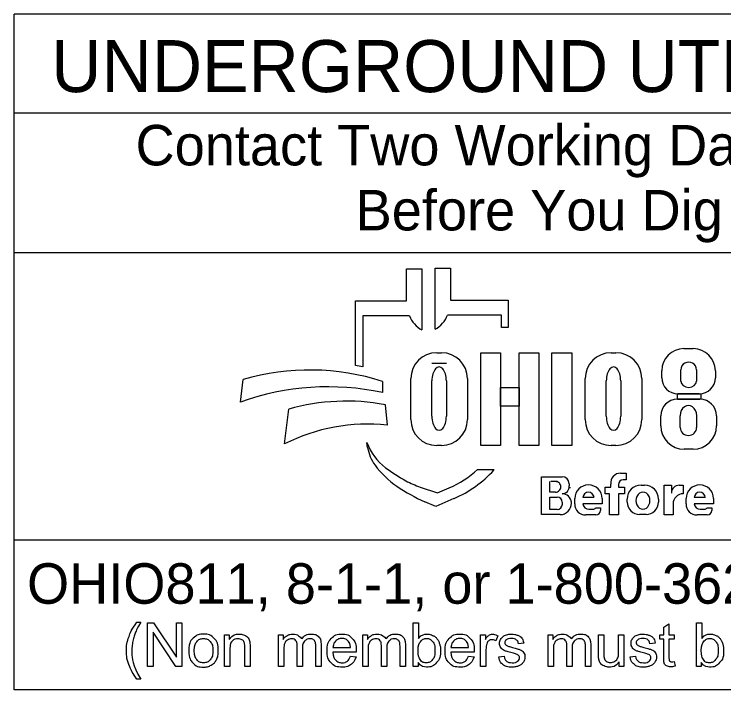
# Model space of a CAD drawing. Extents: x -3.3 to 34, y 0 to 56.8.
# Drawn here: x 2.378 to 4.831, y 1.905 to 4.243 of the extents above; entities that cross this region are included whole.
import ezdxf

# ---------------------------------------------------------------- set-up
doc = ezdxf.new("R2010")
doc.units = 0
doc.layers.add('SH_Data', color=7, linetype='Continuous')
doc.layers.add('SH_Major_Grid_Line', color=7, linetype='Continuous')

msp = doc.modelspace()

# ---------------------------------------------------------------- linework, layer by layer
at = {"layer": 'SH_Data'}
for p, q in [((2.3775, 1.9053), (2.3775, 4.2428)), ((6.6275, 4.2428), (2.3775, 4.2428)), ((2.3775, 3.9012), (6.6275, 3.9012)), ((2.3775, 3.4178), (6.6275, 3.4178)), ((6.6275, 2.4232), (2.3775, 2.4232)), ((6.6275, 1.9053), (2.3775, 1.9053))]:
    msp.add_line(p, q, dxfattribs=at)
at = {"layer": 'SH_Major_Grid_Line'}
for p, q in [((3.7335, 3.2508), (3.7335, 3.3623)), ((3.7335, 3.3623), (3.7872, 3.3623)), ((3.7872, 3.3623), (3.7872, 3.1502)), ((3.8329, 3.1525), (3.8329, 3.3646)), ((3.8329, 3.3646), (3.8865, 3.3646)), ((3.8865, 3.3646), (3.8865, 3.2531)), ((3.5576, 3.0269), (3.5576, 3.2508)), ((3.5576, 3.2508), (3.7335, 3.2508)), ((3.8865, 3.2531), (4.0857, 3.2531)), ((4.0857, 3.2531), (4.0857, 3.1593)), ((3.5828, 3.1994), (3.5828, 3.0225)), ((3.7439, 3.1994), (3.5828, 3.1994)), ((4.0625, 3.2017), (3.8761, 3.2017)), ((4.0625, 3.1593), (4.0625, 3.2017)), ((4.0857, 3.1593), (4.0625, 3.1593)), ((3.8385, 3.0716), (3.8551, 3.0716)), ((4.4416, 3.0716), (4.4581, 3.0716)), ((4.6931, 3.0856), (4.7258, 3.0856)), ((3.8718, 3.0346), (3.822, 3.0346)), ((4.6168, 2.985), (4.6168, 3.0093)), ((4.683, 2.9736), (4.683, 3.0129)), ((4.7371, 3.0129), (4.7371, 2.9736)), ((4.8022, 3.0093), (4.8022, 2.985)), ((3.1602, 2.9006), (3.1696, 2.9787)), ((3.6509, 2.9722), (3.6509, 2.9334)), ((3.7491, 2.8401), (3.7491, 2.9821)), ((3.822, 2.8515), (3.822, 2.9739)), ((3.8718, 2.9739), (3.8718, 2.8515)), ((3.9445, 2.9821), (3.9445, 2.8401)), ((4.3521, 2.8401), (4.3521, 2.9821)), ((4.425, 2.8515), (4.425, 2.9739)), ((4.4748, 2.9739), (4.4748, 2.8515)), ((4.5476, 2.9821), (4.5476, 2.8401)), ((4.7462, 2.929), (4.6728, 2.929)), ((4.671, 2.9107), (4.7483, 2.9107)), ((3.312, 2.7561), (3.3267, 2.8762)), ((3.6608, 2.8916), (3.6671, 2.8207)), ((4.6131, 2.8188), (4.6131, 2.8528)), ((4.6806, 2.8128), (4.6806, 2.8537)), ((4.7374, 2.8537), (4.7374, 2.8128)), ((4.8062, 2.8528), (4.8062, 2.8188)), ((3.5997, 2.7432), (3.5967, 2.7611)), ((3.8551, 2.7507), (3.8385, 2.7507)), ((4.4581, 2.7507), (4.4416, 2.7507)), ((4.7252, 2.7378), (4.6941, 2.7378)), ((3.98, 2.6673), (4.0375, 2.6673)), ((4.4739, 2.6551), (4.4934, 2.6551)), ((4.4934, 2.6551), (4.4934, 2.6321)), ((4.2013, 2.5115), (4.2013, 2.6423)), ((4.2013, 2.6423), (4.2725, 2.6423)), ((4.2293, 2.5888), (4.2293, 2.6257)), ((4.2545, 2.6257), (4.2332, 2.6257)), ((4.4934, 2.6316), (4.4832, 2.6316)), ((3.7816, 2.6069), (3.841, 2.5864)), ((3.841, 2.5864), (3.8821, 2.6042)), ((4.2963, 2.6185), (4.2963, 2.6106)), ((4.4213, 2.5837), (4.4213, 2.6067)), ((4.4213, 2.6067), (4.4406, 2.6067)), ((4.4406, 2.6067), (4.4406, 2.6171)), ((4.4667, 2.6151), (4.4667, 2.6067)), ((4.4667, 2.6067), (4.4883, 2.6067)), ((4.4883, 2.6067), (4.4883, 2.5837)), ((4.5451, 2.6133), (4.5573, 2.6133)), ((4.6254, 2.5103), (4.6254, 2.613)), ((4.6254, 2.613), (4.6499, 2.613)), ((4.6499, 2.613), (4.6499, 2.5862)), ((4.6772, 2.613), (4.691, 2.613)), ((4.691, 2.613), (4.691, 2.5834)), ((4.2487, 2.5888), (4.2293, 2.5888)), ((4.4362, 2.5837), (4.4213, 2.5837)), ((4.4362, 2.5103), (4.4362, 2.5837)), ((4.4883, 2.5837), (4.4667, 2.5837)), ((4.4667, 2.5837), (4.4667, 2.5103)), ((3.835, 2.5394), (3.7976, 2.5559)), ((3.8983, 2.5669), (3.835, 2.5394)), ((4.2293, 2.5294), (4.2293, 2.5722)), ((4.2293, 2.5722), (4.2548, 2.5722)), ((4.2729, 2.5541), (4.2729, 2.5478)), ((4.3159, 2.5483), (4.3159, 2.5667)), ((4.3824, 2.5707), (4.3439, 2.5707)), ((4.4104, 2.5667), (4.4104, 2.5491)), ((4.4973, 2.5547), (4.4973, 2.5654)), ((4.6051, 2.5654), (4.6051, 2.5547)), ((4.7008, 2.5483), (4.7008, 2.5667)), ((4.7674, 2.5707), (4.7288, 2.5707)), ((4.7953, 2.5667), (4.7953, 2.5491)), ((4.2546, 2.5294), (4.2293, 2.5294)), ((4.3043, 2.5512), (4.3043, 2.5509)), ((4.4104, 2.5491), (4.344, 2.5491)), ((4.3649, 2.5298), (4.379, 2.5298)), ((4.3876, 2.5354), (4.4045, 2.5354)), ((4.4045, 2.5354), (4.4045, 2.5256)), ((4.6559, 2.5485), (4.6559, 2.5103)), ((4.7953, 2.5491), (4.7289, 2.5491)), ((4.7498, 2.5298), (4.7639, 2.5298)), ((4.7725, 2.5354), (4.7894, 2.5354)), ((4.7894, 2.5354), (4.7894, 2.5256)), ((4.265, 2.5115), (4.2013, 2.5115)), ((4.3892, 2.5103), (4.3538, 2.5103)), ((4.4667, 2.5103), (4.4362, 2.5103)), ((4.5623, 2.5119), (4.5401, 2.5119)), ((4.6559, 2.5103), (4.6254, 2.5103)), ((4.7742, 2.5103), (4.7388, 2.5103))]:
    msp.add_line(p, q, dxfattribs=at)
for points in [[(3.991, 3.0706), (4.0589, 3.0706), (4.0589, 2.7506), (3.991, 2.7506)], [(4.1231, 3.0706), (4.1911, 3.0706), (4.1911, 2.7506), (4.1231, 2.7506)], [(4.2364, 3.0706), (4.3052, 3.0706), (4.3052, 2.7506), (4.2364, 2.7506)], [(4.0589, 2.9507), (4.1231, 2.9507), (4.1231, 2.8867), (4.0589, 2.8867)], [(4.6706, 2.929), (4.7523, 2.929), (4.7523, 2.9106), (4.6706, 2.9106)]]:
    msp.add_lwpolyline(points, close=True, dxfattribs=at)
for points in [[(2.8021, 2.1391), (2.8153, 2.1391)], [(2.8389, 1.9864), (2.8389, 2.1366), (2.8592, 2.1366), (2.9382, 2.0186), (2.9382, 2.1366), (2.9572, 2.1366), (2.9572, 1.9864), (2.9369, 1.9864), (2.8579, 2.1044), (2.8579, 1.9864), (2.8389, 1.9864)], [(3.7743, 1.9864), (3.7573, 1.9864), (3.7573, 2.1366), (3.7757, 2.1366), (3.7757, 2.0831)], [(4.7534, 1.9864), (4.7363, 1.9864), (4.7363, 2.1366), (4.7548, 2.1366), (4.7548, 2.0831)], [(4.6233, 2.0183), (4.6233, 2.081), (4.6097, 2.081), (4.6097, 2.0953), (4.6233, 2.0953), (4.6233, 2.1222), (4.6417, 2.1333), (4.6417, 2.0953), (4.6601, 2.0953), (4.6601, 2.081), (4.6417, 2.081), (4.6417, 2.0172)], [(3.1048, 1.9864), (3.1048, 2.0953), (3.1214, 2.0953), (3.1214, 2.0798)], [(3.2912, 1.9864), (3.2912, 2.0953), (3.3077, 2.0953), (3.3077, 2.0799)], [(3.5826, 1.9864), (3.5826, 2.0953), (3.5991, 2.0953), (3.5991, 2.0799)], [(3.9904, 1.9864), (3.9904, 2.0953), (4.007, 2.0953), (4.007, 2.0788)], [(4.0495, 2.0918), (4.043, 2.0747)], [(4.2236, 1.9864), (4.2236, 2.0953), (4.2401, 2.0953), (4.2401, 2.0799)], [(4.3979, 2.0279), (4.3979, 2.0953), (4.4164, 2.0953), (4.4164, 2.0349)], [(4.4676, 2.037), (4.4676, 2.0953), (4.4861, 2.0953), (4.4861, 1.9864), (4.4696, 1.9864)], [(4.1394, 2.0671), (4.1213, 2.0647)], [(4.594, 2.0671), (4.5759, 2.0647)], [(3.1233, 2.0458), (3.1233, 1.9864), (3.1048, 1.9864)], [(3.1932, 2.0533), (3.1932, 1.9864), (3.1748, 1.9864), (3.1748, 2.0526)], [(3.3097, 2.0428), (3.3097, 1.9864), (3.2912, 1.9864)], [(3.3743, 2.0496), (3.3743, 1.9864), (3.3559, 1.9864), (3.3559, 2.0571)], [(3.4388, 2.0611), (3.4388, 1.9864), (3.4203, 1.9864), (3.4203, 2.0549)], [(3.4799, 2.0512), (3.5406, 2.0512)], [(3.601, 2.0428), (3.601, 1.9864), (3.5826, 1.9864)], [(3.6657, 2.0496), (3.6657, 1.9864), (3.6473, 1.9864), (3.6473, 2.0571)], [(3.7301, 2.0611), (3.7301, 1.9864), (3.7117, 1.9864), (3.7117, 2.0549)], [(3.8879, 2.0512), (3.9486, 2.0512)], [(4.0088, 2.0434), (4.0088, 1.9864), (3.9904, 1.9864)], [(4.242, 2.0428), (4.242, 1.9864), (4.2236, 1.9864)], [(4.3067, 2.0496), (4.3067, 1.9864), (4.2883, 1.9864), (4.2883, 2.0571)], [(4.3711, 2.0611), (4.3711, 1.9864), (4.3527, 1.9864), (4.3527, 2.0549)], [(3.56, 2.0361), (3.4788, 2.0361)], [(3.5404, 2.0216), (3.5595, 2.0192)], [(3.968, 2.0361), (3.8868, 2.0361)], [(3.9484, 2.0216), (3.9675, 2.0192)], [(4.053, 2.0189), (4.0712, 2.0218)], [(4.5076, 2.0189), (4.5258, 2.0218)], [(3.7743, 2), (3.7743, 1.9864)], [(4.4696, 1.9864), (4.4696, 2.0025)], [(4.6601, 2.0029), (4.6628, 1.9866)], [(4.7534, 2), (4.7534, 1.9864)], [(2.8153, 1.9422), (2.8021, 1.9422)]]:
    msp.add_lwpolyline(points, dxfattribs=at)
for centre, radius, start, end in [((3.8353, 3.2361), 0.0985, 201.9296, 240.7469), ((3.7847, 3.2385), 0.0985, 299.2531, 338.0704), ((3.8385, 2.9821), 0.0895, 90, 180), ((3.8551, 2.9821), 0.0895, 0, 90), ((4.4416, 2.9821), 0.0895, 90, 180), ((4.4581, 2.9821), 0.0895, 0, 90), ((4.6931, 3.0093), 0.0763, 90, 180), ((4.7258, 3.0093), 0.0763, 0, 90), ((3.4295, 2.2179), 0.8191, 79.2074, 81.0007), ((3.3997, 2.1927), 0.8191, 72.1402, 106.3144), ((4.6728, 2.985), 0.056, 180, 270), ((4.7462, 2.985), 0.056, 270, 0), ((3.4628, 2.0616), 0.8919, 77.8238, 109.8274), ((3.5267, 2.1719), 0.7322, 79.44, 105.8467), ((4.671, 2.8528), 0.0579, 90, 180), ((4.7483, 2.8528), 0.0579, 0, 90), ((3.5987, 2.1887), 0.6357, 83.8248, 116.8021), ((3.8385, 2.8401), 0.0895, 180, 270), ((3.8551, 2.8401), 0.0895, 270, 0), ((4.4416, 2.8401), 0.0895, 180, 270), ((4.4581, 2.8401), 0.0895, 270, 0), ((4.6941, 2.8188), 0.081, 180, 270), ((4.7252, 2.8188), 0.081, 270, 0), ((3.7841, 2.8332), 0.2008, 201.0457, 232.5314), ((3.741, 2.7673), 0.1433, 189.6817, 216.0884), ((3.8747, 2.8647), 0.3088, 216.0884, 235.7167), ((3.9766, 3.0844), 0.5173, 232.5314, 241.794), ((3.7387, 2.9347), 0.3602, 293.4582, 312.0712), ((3.7387, 2.9347), 0.401, 293.4582, 317.8286), ((4.4739, 2.6215), 0.0335, 90, 187.5187), ((3.8914, 2.9256), 0.3371, 241.794, 250.9821), ((4.2505, 2.6088), 0.0169, 357.8325, 90), ((4.2725, 2.6185), 0.0238, 0, 90), ((4.4832, 2.6151), 0.0165, 90, 180), ((4.0412, 3.109), 0.6044, 235.7167, 246.2325), ((4.2487, 2.6075), 0.0187, 270, 2.0582), ((4.2721, 2.6078), 0.0243, 270, 6.6529), ((4.2827, 2.6063), 0.0175, 347.4023, 0), ((4.3631, 2.5667), 0.0473, 0, 180), ((4.5451, 2.5654), 0.0478, 90, 180), ((4.5573, 2.5654), 0.0478, 0, 90), ((4.6768, 2.5862), 0.0269, 89.2449, 180), ((4.7481, 2.5667), 0.0473, 0, 180), ((4.2722, 2.5514), 0.0321, 4.0748, 90), ((4.3632, 2.5697), 0.0193, 2.9632, 177.0368), ((4.6908, 2.5485), 0.0349, 89.6033, 180), ((4.7481, 2.5697), 0.0193, 2.9632, 177.0368), ((4.2548, 2.5541), 0.0181, 0, 90), ((4.2714, 2.5512), 0.033, 0, 11.7502), ((4.5401, 2.5547), 0.0428, 180, 270), ((4.5623, 2.5547), 0.0428, 270, 0), ((4.2546, 2.5478), 0.0184, 270, 0), ((4.265, 2.5509), 0.0393, 270, 0), ((4.3538, 2.5483), 0.038, 180, 270), ((4.3649, 2.5508), 0.021, 184.827, 270), ((4.379, 2.5392), 0.00938, 270, 335.9979), ((4.7388, 2.5483), 0.038, 180, 270), ((4.7498, 2.5508), 0.021, 184.827, 270), ((4.7639, 2.5392), 0.00938, 270, 335.9979), ((4.3892, 2.5256), 0.0152, 270, 0), ((4.7742, 2.5256), 0.0152, 270, 0)]:
    msp.add_arc(centre, radius, start, end, dxfattribs=at)
for centre, major_axis, ratio, start_param, end_param in [((3.8469, 2.9739), (0, 0.0484), 0.514403, 4.712389, 7.853982), ((4.4499, 2.9739), (0, 0.0484), 0.514403, 4.712389, 7.853982), ((4.71, 3.0129), (0.0271, 0), 0.969373, 0, 3.141593), ((4.71, 2.9736), (0.0271, 0), 0.818453, 3.141593, 6.283185), ((4.709, 2.8537), (0, 0.0358), 0.794529, 4.712389, 7.853982), ((3.8469, 2.8515), (0, 0.0484), 0.514403, 1.570796, 4.712389), ((4.4499, 2.8515), (0, 0.0484), 0.514403, 1.570796, 4.712389), ((4.709, 2.8128), (0.0284, 0), 0.959837, 3.141593, 6.283185), ((4.5517, 2.5601), (0, 0.029), 0.832186, 4.712389, 7.853982), ((4.5517, 2.5601), (0, 0.0302), 0.797287, 1.570796, 4.712389)]:
    msp.add_ellipse(centre, major_axis=major_axis, ratio=ratio, start_param=start_param, end_param=end_param, dxfattribs=at)
for points in [[(2.8021, 1.9422), (2.7869, 1.9615), (2.7763, 1.9873), (2.7657, 2.0131), (2.7657, 2.0408), (2.7657, 2.0651), (2.7736, 2.0875), (2.7829, 2.1134), (2.8021, 2.1391)], [(2.8153, 2.1391), (2.8029, 2.1178), (2.7989, 2.1087), (2.7927, 2.0945), (2.7891, 2.0792), (2.7847, 2.06), (2.7847, 2.0407), (2.7847, 1.9914), (2.8153, 1.9422)], [(2.9814, 2.0408), (2.9814, 2.071), (2.9981, 2.0856), (3.0122, 2.0977), (3.0323, 2.0977), (3.0547, 2.0977), (3.069, 2.083), (3.0832, 2.0683), (3.0832, 2.0424), (3.0832, 2.0214), (3.0769, 2.0094), (3.0706, 1.9973), (3.0586, 1.9907), (3.0466, 1.984), (3.0323, 1.984), (3.0095, 1.984), (2.9954, 1.9987), (2.9814, 2.0133), (2.9814, 2.0408)], [(3.1214, 2.0798), (3.1334, 2.0977), (3.156, 2.0977), (3.1659, 2.0977), (3.1741, 2.0941), (3.1823, 2.0906), (3.1864, 2.0849), (3.1905, 2.0791), (3.1922, 2.0712), (3.1932, 2.0661), (3.1932, 2.0533)], [(3.3077, 2.0799), (3.3128, 2.0879), (3.3214, 2.0928), (3.3299, 2.0977), (3.3407, 2.0977), (3.3528, 2.0977), (3.3606, 2.0926), (3.3683, 2.0876), (3.3715, 2.0786), (3.3844, 2.0977), (3.4051, 2.0977), (3.4213, 2.0977), (3.43, 2.0887), (3.4388, 2.0797), (3.4388, 2.0611)], [(3.5595, 2.0192), (3.555, 2.0025), (3.5428, 1.9932), (3.5306, 1.984), (3.5117, 1.984), (3.4878, 1.984), (3.4738, 1.9987), (3.4598, 2.0134), (3.4598, 2.0399), (3.4598, 2.0674), (3.474, 2.0825), (3.4881, 2.0977), (3.5106, 2.0977), (3.5324, 2.0977), (3.5463, 2.0828), (3.5601, 2.068), (3.5601, 2.041), (3.5601, 2.0394), (3.56, 2.0361)], [(3.5991, 2.0799), (3.6042, 2.0879), (3.6127, 2.0928), (3.6212, 2.0977), (3.6321, 2.0977), (3.6442, 2.0977), (3.6519, 2.0926), (3.6597, 2.0876), (3.6628, 2.0786), (3.6758, 2.0977), (3.6965, 2.0977), (3.7127, 2.0977), (3.7214, 2.0887), (3.7301, 2.0797), (3.7301, 2.0611)], [(3.7757, 2.0831), (3.7874, 2.0977), (3.8055, 2.0977), (3.8155, 2.0977), (3.8245, 2.0936), (3.8335, 2.0896), (3.8392, 2.0823), (3.845, 2.0749), (3.8483, 2.0646), (3.8516, 2.0543), (3.8516, 2.0425), (3.8516, 2.0145), (3.8378, 1.9993), (3.8239, 1.984), (3.8046, 1.984), (3.7853, 1.984), (3.7743, 2)], [(3.9675, 2.0192), (3.963, 2.0025), (3.9508, 1.9932), (3.9386, 1.984), (3.9196, 1.984), (3.8958, 1.984), (3.8818, 1.9987), (3.8678, 2.0134), (3.8678, 2.0399), (3.8678, 2.0674), (3.882, 2.0825), (3.8961, 2.0977), (3.9186, 2.0977), (3.9404, 2.0977), (3.9543, 2.0828), (3.9681, 2.068), (3.9681, 2.041), (3.9681, 2.0394), (3.968, 2.0361)], [(4.007, 2.0788), (4.0133, 2.0903), (4.0187, 2.094), (4.0241, 2.0977), (4.0305, 2.0977), (4.0398, 2.0977), (4.0495, 2.0918)], [(4.0712, 2.0218), (4.0727, 2.0108), (4.0798, 2.005), (4.0868, 1.9991), (4.0995, 1.9991), (4.1122, 1.9991), (4.1184, 2.0043), (4.1245, 2.0095), (4.1245, 2.0165), (4.1245, 2.0227), (4.1191, 2.0263), (4.1153, 2.0288), (4.1002, 2.0326), (4.0799, 2.0377), (4.072, 2.0414), (4.0642, 2.0452), (4.0601, 2.0518), (4.0561, 2.0584), (4.0561, 2.0663), (4.0561, 2.0736), (4.0594, 2.0798), (4.0628, 2.086), (4.0685, 2.0901), (4.0728, 2.0933), (4.0803, 2.0955), (4.0877, 2.0977), (4.0962, 2.0977), (4.109, 2.0977), (4.1187, 2.094), (4.1284, 2.0903), (4.133, 2.084), (4.1377, 2.0777), (4.1394, 2.0671)], [(4.2401, 2.0799), (4.2452, 2.0879), (4.2537, 2.0928), (4.2622, 2.0977), (4.2731, 2.0977), (4.2852, 2.0977), (4.2929, 2.0926), (4.3007, 2.0876), (4.3038, 2.0786), (4.3168, 2.0977), (4.3375, 2.0977), (4.3537, 2.0977), (4.3624, 2.0887), (4.3711, 2.0797), (4.3711, 2.0611)], [(4.5258, 2.0218), (4.5273, 2.0108), (4.5343, 2.005), (4.5414, 1.9991), (4.554, 1.9991), (4.5668, 1.9991), (4.5729, 2.0043), (4.5791, 2.0095), (4.5791, 2.0165), (4.5791, 2.0227), (4.5736, 2.0263), (4.5698, 2.0288), (4.5548, 2.0326), (4.5345, 2.0377), (4.5266, 2.0414), (4.5188, 2.0452), (4.5147, 2.0518), (4.5107, 2.0584), (4.5107, 2.0663), (4.5107, 2.0736), (4.514, 2.0798), (4.5173, 2.086), (4.5231, 2.0901), (4.5274, 2.0933), (4.5348, 2.0955), (4.5423, 2.0977), (4.5508, 2.0977), (4.5636, 2.0977), (4.5733, 2.094), (4.583, 2.0903), (4.5876, 2.084), (4.5922, 2.0777), (4.594, 2.0671)], [(4.7548, 2.0831), (4.7664, 2.0977), (4.7846, 2.0977), (4.7946, 2.0977), (4.8036, 2.0936), (4.8125, 2.0896), (4.8183, 2.0823), (4.8241, 2.0749), (4.8274, 2.0646), (4.8306, 2.0543), (4.8306, 2.0425), (4.8306, 2.0145), (4.8168, 1.9993), (4.803, 1.984), (4.7836, 1.984), (4.7644, 1.984), (4.7534, 2)], [(3.0003, 2.0408), (3.0003, 2.0199), (3.0094, 2.0095), (3.0185, 1.9991), (3.0323, 1.9991), (3.046, 1.9991), (3.0551, 2.0096), (3.0642, 2.02), (3.0642, 2.0415), (3.0642, 2.0616), (3.0551, 2.072), (3.0459, 2.0824), (3.0323, 2.0824), (3.0185, 2.0824), (3.0094, 2.0721), (3.0003, 2.0617), (3.0003, 2.0408)], [(3.1748, 2.0526), (3.1748, 2.0638), (3.1726, 2.0694), (3.1705, 2.075), (3.165, 2.0783), (3.1595, 2.0816), (3.1521, 2.0816), (3.1404, 2.0816), (3.1318, 2.0742), (3.1233, 2.0667), (3.1233, 2.0458)], [(3.3559, 2.0571), (3.3559, 2.0694), (3.3514, 2.0755), (3.3469, 2.0816), (3.3366, 2.0816), (3.3288, 2.0816), (3.3222, 2.0775), (3.3156, 2.0735), (3.3126, 2.0656), (3.3097, 2.0577), (3.3097, 2.0428)], [(3.4203, 2.0549), (3.4203, 2.066), (3.4185, 2.0708), (3.4168, 2.0757), (3.412, 2.0787), (3.4073, 2.0816), (3.401, 2.0816), (3.3895, 2.0816), (3.3819, 2.074), (3.3743, 2.0664), (3.3743, 2.0496)], [(3.5406, 2.0512), (3.5394, 2.065), (3.5337, 2.0719), (3.5249, 2.0826), (3.5108, 2.0826), (3.4981, 2.0826), (3.4894, 2.074), (3.4808, 2.0655), (3.4799, 2.0512)], [(3.6473, 2.0571), (3.6473, 2.0694), (3.6428, 2.0755), (3.6383, 2.0816), (3.628, 2.0816), (3.6202, 2.0816), (3.6136, 2.0775), (3.607, 2.0735), (3.604, 2.0656), (3.601, 2.0577), (3.601, 2.0428)], [(3.7117, 2.0549), (3.7117, 2.066), (3.7099, 2.0708), (3.7081, 2.0757), (3.7034, 2.0787), (3.6987, 2.0816), (3.6923, 2.0816), (3.6809, 2.0816), (3.6733, 2.074), (3.6657, 2.0664), (3.6657, 2.0496)], [(3.7741, 2.0417), (3.7741, 2.0221), (3.7794, 2.0134), (3.7881, 1.9991), (3.8029, 1.9991), (3.815, 1.9991), (3.8238, 2.0096), (3.8326, 2.0201), (3.8326, 2.0409), (3.8326, 2.0623), (3.8241, 2.0724), (3.8157, 2.0826), (3.8038, 2.0826), (3.7917, 2.0826), (3.7829, 2.0721), (3.7741, 2.0615), (3.7741, 2.0417)], [(3.9486, 2.0512), (3.9474, 2.065), (3.9417, 2.0719), (3.9328, 2.0826), (3.9188, 2.0826), (3.9061, 2.0826), (3.8974, 2.074), (3.8888, 2.0655), (3.8879, 2.0512)], [(4.043, 2.0747), (4.0363, 2.0787), (4.0295, 2.0787), (4.0235, 2.0787), (4.0187, 2.075), (4.0139, 2.0714), (4.0119, 2.0649), (4.0088, 2.0551), (4.0088, 2.0434)], [(4.1213, 2.0647), (4.1201, 2.0731), (4.1142, 2.0778), (4.1083, 2.0826), (4.0975, 2.0826), (4.0848, 2.0826), (4.0794, 2.0784), (4.0739, 2.0741), (4.0739, 2.0685), (4.0739, 2.0649), (4.0762, 2.062), (4.0785, 2.0591), (4.0833, 2.0571), (4.086, 2.0561), (4.0996, 2.0524), (4.1192, 2.0472), (4.1269, 2.0438), (4.1347, 2.0405), (4.1391, 2.0342), (4.1435, 2.0278), (4.1435, 2.0184), (4.1435, 2.0092), (4.1381, 2.0011), (4.1327, 1.9929), (4.1226, 1.9885), (4.1124, 1.984), (4.0996, 1.984), (4.0784, 1.984), (4.0672, 1.9928), (4.0561, 2.0016), (4.053, 2.0189)], [(4.2883, 2.0571), (4.2883, 2.0694), (4.2838, 2.0755), (4.2793, 2.0816), (4.269, 2.0816), (4.2612, 2.0816), (4.2546, 2.0775), (4.248, 2.0735), (4.245, 2.0656), (4.242, 2.0577), (4.242, 2.0428)], [(4.3527, 2.0549), (4.3527, 2.066), (4.3509, 2.0708), (4.3491, 2.0757), (4.3444, 2.0787), (4.3397, 2.0816), (4.3333, 2.0816), (4.3219, 2.0816), (4.3143, 2.074), (4.3067, 2.0664), (4.3067, 2.0496)], [(4.5759, 2.0647), (4.5747, 2.0731), (4.5688, 2.0778), (4.5629, 2.0826), (4.5521, 2.0826), (4.5394, 2.0826), (4.5339, 2.0784), (4.5285, 2.0741), (4.5285, 2.0685), (4.5285, 2.0649), (4.5308, 2.062), (4.533, 2.0591), (4.5378, 2.0571), (4.5406, 2.0561), (4.5542, 2.0524), (4.5737, 2.0472), (4.5815, 2.0438), (4.5893, 2.0405), (4.5937, 2.0342), (4.5981, 2.0278), (4.5981, 2.0184), (4.5981, 2.0092), (4.5927, 2.0011), (4.5873, 1.9929), (4.5772, 1.9885), (4.567, 1.984), (4.5542, 1.984), (4.5329, 1.984), (4.5218, 1.9928), (4.5107, 2.0016), (4.5076, 2.0189)], [(4.7532, 2.0417), (4.7532, 2.0221), (4.7585, 2.0134), (4.7672, 1.9991), (4.782, 1.9991), (4.7941, 1.9991), (4.8029, 2.0096), (4.8116, 2.0201), (4.8116, 2.0409), (4.8116, 2.0623), (4.8032, 2.0724), (4.7948, 2.0826), (4.7828, 2.0826), (4.7708, 2.0826), (4.762, 2.0721), (4.7532, 2.0615), (4.7532, 2.0417)], [(4.4164, 2.0349), (4.4164, 2.0205), (4.4175, 2.0155), (4.4192, 2.0082), (4.4249, 2.0041), (4.4305, 1.9999), (4.4388, 1.9999), (4.4471, 1.9999), (4.4543, 2.0042), (4.4616, 2.0084), (4.4646, 2.0158), (4.4676, 2.0231), (4.4676, 2.037)], [(3.4788, 2.0361), (3.4799, 2.0182), (3.489, 2.0087), (3.4981, 1.9991), (3.5117, 1.9991), (3.5219, 1.9991), (3.5291, 2.0045), (3.5362, 2.0098), (3.5404, 2.0216)], [(3.8868, 2.0361), (3.8879, 2.0182), (3.897, 2.0087), (3.9061, 1.9991), (3.9197, 1.9991), (3.9299, 1.9991), (3.937, 2.0045), (3.9442, 2.0098), (3.9484, 2.0216)], [(4.4696, 2.0025), (4.4569, 1.984), (4.4351, 1.984), (4.4255, 1.984), (4.4171, 1.9877), (4.4088, 1.9914), (4.4047, 1.997), (4.4007, 2.0026), (4.3991, 2.0107), (4.3979, 2.0161), (4.3979, 2.0279)], [(4.6628, 1.9866), (4.655, 1.9849), (4.6488, 1.9849), (4.6388, 1.9849), (4.6333, 1.9881), (4.6278, 1.9913), (4.6255, 1.9965), (4.6233, 2.0017), (4.6233, 2.0183)], [(4.6417, 2.0172), (4.6417, 2.0093), (4.6427, 2.007), (4.6436, 2.0048), (4.6458, 2.0034), (4.648, 2.0021), (4.6521, 2.0021), (4.6551, 2.0021), (4.6601, 2.0029)]]:
    msp.add_open_spline(points, degree=3, dxfattribs=at)

# ---------------------------------------------------------------- texts
for s, height, p in [('UNDERGROUND UTILITIES', 0.18, (2.5057, 3.9731)), ('Contact Two Working Days', 0.14, (2.7972, 3.7196)), ('Before You Dig', 0.14, (3.5583, 3.4946)), ('OHIO811, 8-1-1, or 1-800-362-2764', 0.14, (2.422, 2.2031))]:
    msp.add_text(s, height=height, dxfattribs=at).set_placement(p)

doc.saveas('drawing.dxf')
